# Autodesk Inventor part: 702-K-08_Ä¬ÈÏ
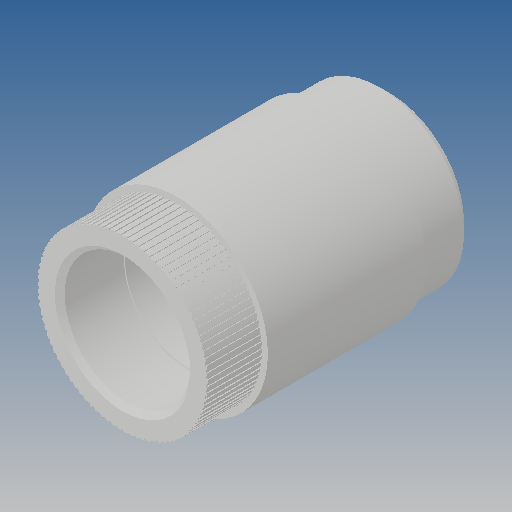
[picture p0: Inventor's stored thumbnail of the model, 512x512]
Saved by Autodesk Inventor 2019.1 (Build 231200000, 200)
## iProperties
Created: 2010-06
Part Number: 702-K-08_Ä¬ÈÏ
Material: Ogólny
Document SubType Name: Modeling
Designer: CADENGINEERING4
Density: 1 g/cm^3
Appearance: Domyślna
Author: CADENGINEERING4
Revision Number: ÈÎºÎ
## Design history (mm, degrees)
feature "NONE"
node "Bryła1"
